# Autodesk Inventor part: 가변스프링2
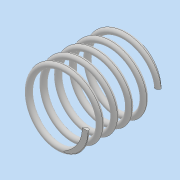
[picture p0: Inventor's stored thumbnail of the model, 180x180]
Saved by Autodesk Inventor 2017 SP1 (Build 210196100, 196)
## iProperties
Part Number: 가변스프링2
Material: 일반
Document SubType Name: Modeling
Designer: MRC
Density: 1 g/cm^3
Appearance: 기본값
Mass: 1.06772 g
Surface Area: 21.6559 cm^2
Volume: 1.06772 cm^3
Author: MRC
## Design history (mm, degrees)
sketch "스케치1"
  geometry: L1 (0, 0)-(0, 25.358); L2 (0, 0)-(11, 0); L3 (0, 25.358)-(11, 25.358); C1 r 1 at (11, 0)
  constraints: 6 end point, 2 horizontal, 1 centre point, 1 coincident, 1 vertical
  dimensions: "d0" = 25.35829 distance of L1.start L1.end (derived); "d1" = 2 diameter of C1; "d2" = 22 diameter of L2.end L1
feature "코일1" sketch "스케치1" pitch "d3" = 10; turns "d5" = 5; dims "d4" = 25.35829 (= d0), "d6" = 0, angle "d7" = 90 deg, angle "d8" = 90 deg, "d9" = 0, "d10" = 0
sketch "스케치2"
  geometry: L1 (15, 0)-(-15, 0); L2 (-15, 0)-(-15, 25.358); L3 (-15, 25.358)-(15, 25.358); L4 (15, 25.358)-(15, 0); 1 further point
  constraints: 8 end point, 2 parallel, 1 horizontal, 1 midpoint, 1 perpendicular
  dimensions: "d11" = 25.35829 distance of L3.end L1.start (= d0); "d12" = 30 distance between parallel lines of L2 L4; "d13" = 15 distance from line of point (0, 0) L4 (= 0.5 x d12)
extrude "돌출1" sketch "스케치2" stored distance "d14" = 30; taper "d15" = 0 deg
node "솔리드1"
